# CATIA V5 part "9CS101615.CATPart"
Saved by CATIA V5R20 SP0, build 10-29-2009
Part number: 9CS101615
Revision: ANY
Definition: UNKNOWN
Nomenclature: 9CS101615
Source: Unknown
Bounding box of the stored display mesh (mm): x -8 to 8, y -7.5 to 7.5, z -8 to 8
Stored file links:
  C:\Users\Utente\Desktop\IO LAVORO\3D X SITO CF\CUMSA\3D files PW\pw101630\pw101630_ejection\9CS101615.CATPart
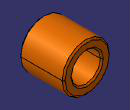
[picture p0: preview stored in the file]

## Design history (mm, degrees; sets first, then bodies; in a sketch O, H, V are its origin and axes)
Body1 "Revolución1" (main body)
  Solid1: solid without history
